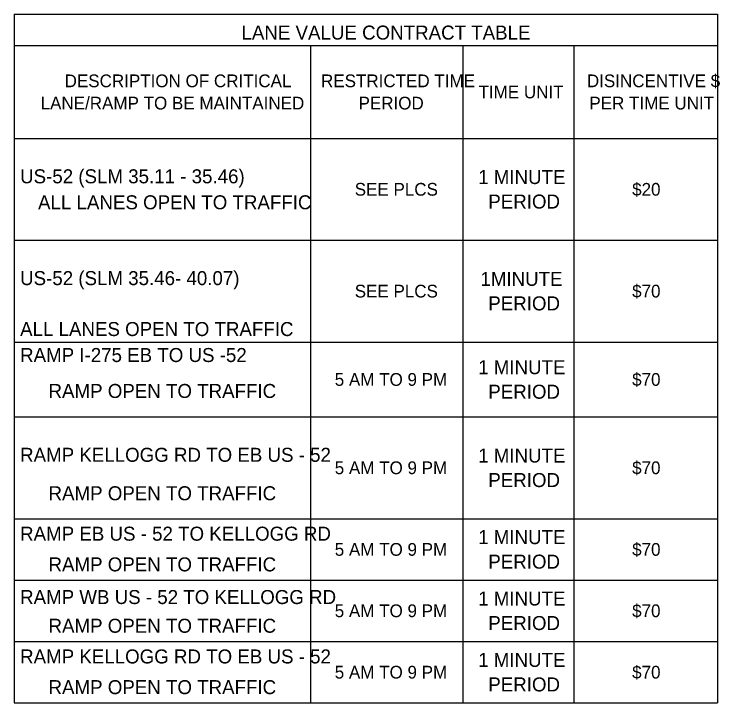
# Model space of a CAD drawing. Extents: x -40 to 107, y -47 to 37.
# Drawn here: x -40.04 to -32.27, y 15.82 to 23.39 of the extents above; entities that cross this region are included whole.
import ezdxf

# ---------------------------------------------------------------- set-up
doc = ezdxf.new("R2010")
doc.units = 0
doc.layers.add('Default', color=7, linetype='Continuous')

msp = doc.modelspace()

# ---------------------------------------------------------------- linework, layer by layer
at = {"layer": 'Default'}
for p, q in [((-40.0353, 23.3918), (-32.2942, 23.3918)), ((-40.0353, 23.3918), (-40.0353, 15.8153)), ((-32.2942, 23.3918), (-32.2942, 15.8153)), ((-40.0353, 23.0459), (-36.7742, 23.0459)), ((-36.7742, 23.0459), (-32.2942, 23.0459)), ((-36.7742, 23.0459), (-36.7742, 15.8153)), ((-35.0942, 23.0459), (-35.0942, 15.8153)), ((-33.8753, 23.0459), (-33.8753, 15.8153)), ((-40.0353, 22.0247), (-32.2942, 22.0247)), ((-40.0353, 20.9047), (-32.2942, 20.9047)), ((-40.0353, 19.7847), (-32.2942, 19.7847)), ((-40.0353, 18.9612), (-32.2942, 18.9612)), ((-40.0353, 17.8412), (-32.2942, 17.8412)), ((-40.0353, 17.1659), (-32.2942, 17.1659)), ((-40.0353, 16.4906), (-32.2942, 16.4906)), ((-40.0353, 15.8153), (-32.2942, 15.8153))]:
    msp.add_line(p, q, dxfattribs=at)

# ---------------------------------------------------------------- texts
for s, height, p in [('LANE VALUE CONTRACT TABLE', 0.154, (-37.5324, 23.1118)), ('DESCRIPTION OF CRITICAL ', 0.14, (-39.4793, 22.5878)), ('RESTRICTED TIME ', 0.14, (-36.657, 22.5878)), ('DISINCENTIVE $ ', 0.14, (-33.7301, 22.5878)), ('TIME UNIT', 0.14, (-34.9231, 22.4653)), ('LANE/RAMP TO BE MAINTAINED', 0.14, (-39.7435, 22.3428)), ('PERIOD', 0.14, (-36.2439, 22.3428)), ('PER TIME UNIT', 0.14, (-33.7027, 22.3428)), ('US-52 (SLM 35.11 - 35.46)', 0.154, (-39.9695, 21.5306)), ('1 MINUTE ', 0.154, (-34.927, 21.5225)), ('SEE PLCS', 0.14, (-36.2859, 21.3947)), ('$20', 0.14, (-33.2322, 21.3947)), ('ALL LANES OPEN TO TRAFFIC', 0.154, (-39.7718, 21.2448)), ('PERIOD', 0.154, (-34.8158, 21.253)), ('US-52 (SLM 35.46- 40.07)', 0.154, (-39.9695, 20.4106)), ('1MINUTE ', 0.154, (-34.9023, 20.4025)), ('SEE PLCS', 0.14, (-36.2859, 20.2747)), ('$70', 0.14, (-33.2322, 20.2747)), ('PERIOD', 0.154, (-34.8158, 20.133)), ('ALL LANES OPEN TO TRAFFIC', 0.154, (-39.9695, 19.8506)), ('RAMP I-275 EB TO US -52', 0.154, (-39.9695, 19.5648)), ('1 MINUTE ', 0.154, (-34.927, 19.4307)), ('5 AM TO 9 PM', 0.14, (-36.5058, 19.3029)), ('$70', 0.14, (-33.2322, 19.3029)), ('RAMP OPEN TO TRAFFIC', 0.154, (-39.6565, 19.1695)), ('PERIOD', 0.154, (-34.8158, 19.1612)), ('RAMP KELLOGG RD TO EB US - 52', 0.154, (-39.9695, 18.4671)), ('1 MINUTE ', 0.154, (-34.927, 18.4589)), ('5 AM TO 9 PM', 0.14, (-36.5058, 18.3312)), ('$70', 0.14, (-33.2322, 18.3312)), ('PERIOD', 0.154, (-34.8158, 18.1894)), ('RAMP OPEN TO TRAFFIC', 0.154, (-39.6565, 18.0442)), ('RAMP EB US - 52 TO KELLOGG RD', 0.154, (-39.9695, 17.5995)), ('1 MINUTE ', 0.154, (-34.927, 17.5613)), ('5 AM TO 9 PM', 0.14, (-36.5058, 17.4335)), ('$70', 0.14, (-33.2322, 17.4335)), ('RAMP OPEN TO TRAFFIC', 0.154, (-39.6565, 17.2618)), ('PERIOD', 0.154, (-34.8158, 17.2918)), ('RAMP WB US - 52 TO KELLOGG RD', 0.154, (-39.9695, 16.9024)), ('1 MINUTE ', 0.154, (-34.927, 16.886)), ('5 AM TO 9 PM', 0.14, (-36.5058, 16.7582)), ('$70', 0.14, (-33.2322, 16.7582)), ('RAMP OPEN TO TRAFFIC', 0.154, (-39.6565, 16.5865)), ('PERIOD', 0.154, (-34.8158, 16.6165)), ('RAMP KELLOGG RD TO EB US - 52', 0.154, (-39.9695, 16.2489)), ('1 MINUTE ', 0.154, (-34.927, 16.2107)), ('5 AM TO 9 PM', 0.14, (-36.5058, 16.0829)), ('$70', 0.14, (-33.2322, 16.0829)), ('PERIOD', 0.154, (-34.8158, 15.9412)), ('RAMP OPEN TO TRAFFIC', 0.154, (-39.6565, 15.9112))]:
    msp.add_text(s, height=height, dxfattribs=at).set_placement(p)

doc.saveas('drawing.dxf')
